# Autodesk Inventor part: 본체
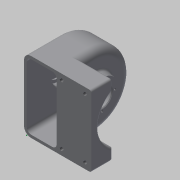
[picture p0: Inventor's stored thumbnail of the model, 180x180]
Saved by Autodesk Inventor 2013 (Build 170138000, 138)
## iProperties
Created: 2015-02
Part Number: 본체
Material: 일반
Document SubType Name: Modeling
Designer: Administrator
Density: 1 g/cm^3
Author: Administrator
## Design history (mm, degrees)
sketch "스케치1"
  geometry: L1 (0, 0)-(95, 0); L2 (95, 0)-(95, 100); L3 (95, 100)-(0, 100); L4 (0, 100)-(0, 0); 4 further points
  constraints: 8 end point, 2 parallel, 1 horizontal, 1 perpendicular
  dimensions: "d0" = 100 distance of L1.end L2.end; "d2" = 95 distance of L2.end L3.end; "d3" = 9 distance from line of L4 point (9, 91.75); "d4" = 33 distance of point (9, 91.75) point (42, 91.75); "d5" = 9 distance from line of L4 point (9, 8.25); "d6" = 33 distance of point (9, 8.25) point (42, 8.25); "d7" = 83.5 distance of point (9, 91.75) point (9, 8.25); "d8" = 8.25 distance from line of L3 point (9, 91.75); "d9" = 8.25 distance from line of L1 point (42, 8.25); "d10" = 8.25 distance from line of L3 point (42, 91.75)
extrude "돌출1" new body sketch "스케치1" distance "d11" = 30; taper "d12" = 0 deg
node "작업 평면1"
sketch "스케치2"
  geometry: L1 (0, 30)-(100, 30) reference; L2 (0, 0)-(0, 30) reference; L3 (100, 0)-(100, 30) reference; L4 (0, 0)-(100, 0) reference; C1 r 50 at (50, 50); C2 r 20 at (50, 50); 1 further point
  constraints: 2 centre point, 1 coincident, 1 midpoint, 1 vertical alignment
  dimensions: "d14" = 100 diameter of C1; "d16" = 50 distance from line of L4 C1.centre; "d17" = 40 diameter of C2
extrude "돌출2" join sketch "스케치2" distance "d18" = 50; taper "d19" = 0 deg
extrude "돌출3" join sketch "스케치2" distance "d20" = 9; taper "d21" = 0 deg
node "작업 평면2"
sketch "스케치3"
  geometry: L1 (-45, 4.174)-(-45, 95.826) reference; L2 (-45, 50)-(-35, 50); L3 (-35, 50)-(-35, 73.237); L4 (-35, 73.237)-(-45, 75); 1 further point
  constraints: 6 end point, 2 perpendicular, 1 midpoint, 1 point on line
  dimensions: "d23" = 50 diameter of L4.end L2; "d25" = 100 deg angle of L1 L4; "d27" = 10 distance of L2.start L2.end
revolve "회전1" stored, may be unused: angle "d28" = 90 deg
sketch "스케치4"
  geometry: L1 (0, 30)-(4.174, 30) reference; L2 (0, 0)-(0, 30) reference; L3 (0, 30)-(0, 50); L4 (100, 0)-(100, 30) reference; L5 (95.826, 30)-(100, 30) reference; L6 (100, 30)-(100, 50); L7 (100, 30)-(0, 30); A1 r 50 centre (50, 50) between (4.174, 30) and (0, 50) reference; A2 r 50 centre (50, 50) between (0, 50) and (100, 50); A3 r 50 centre (50, 50) between (95.826, 30) and (4.174, 30) reference
  constraints: 6 end point, 4 point on circle, 2 tangent, 1 centre point, 1 coincident, 1 perpendicular
extrude "돌출4" join sketch "스케치4" distance "d29" = 50; taper "d30" = 0 deg
node "작업 평면3"
sketch "스케치5"
  geometry: C1 r 40 at (50, 50); A1 r 50 centre (50, 50) between (100, 50) and (0, 50) reference; 1 further point
  constraints: 1 centre point, 1 coincident
extrude "돌출5" cut sketch "스케치5" distance "d32" = 45; taper "d33" = 0 deg
revolve "회전2" stored, may be unused: angle "d34" = 90 deg
node "작업 평면4"
sketch "스케치6"
  geometry: L1 (0, 0)-(0, 30) reference; L2 (100, 0)-(0, 0) reference; L3 (0, 30)-(0, 50) reference; L4 (100, 50)-(100, 30) reference; L5 (100, 0)-(100, 30) reference; L6 (4, 4)-(96, 4); L7 (4, 4)-(4, 50); L8 (96, 4)-(96, 50); A1 r 50 centre (50, 50) between (100, 50) and (0, 50) reference; A2 r 46 centre (50, 50) between (96, 50) and (4, 50)
  constraints: 6 end point, 2 perpendicular, 2 point on circle, 1 centre point, 1 coincident, 1 parallel
  dimensions: "d35" = 4 distance between parallel lines of L2 L6; "d36" = 4 distance between parallel lines of L1 L7; "d37" = 4 distance between parallel lines of L5 L8; "d38" = 4 radial gap between concentric circles of A2 A1
extrude "돌출6" cut sketch "스케치6" stored distance "d39" = 42; taper "d40" = 0 deg
hole "구멍1" diameter "d43" = 28; stored, may be unused: countersink angle "d47" = 90 deg, drill point angle "d49" = 0 deg; dims "d41" = 10, "d42" = 10, "d44" = 6, "d45" = 4, "d46" = 2, "d48" = 10
hole "구멍2" diameter "d52" = 20; stored, may be unused: countersink angle "d56" = 90 deg, drill point angle "d58" = 0 deg; dims "d50" = 10, "d51" = 10, "d53" = 6, "d54" = 4, "d55" = 2, "d57" = 4
sketch "스케치7"
  geometry: L1 (0, 0)-(-95, 0) reference; L2 (-95, 100)-(0, 100) reference; L3 (-95, 0)-(-95, 100) reference; L4 (-91, 96)-(-91, 4); L5 (-91, 4)-(-49, 4); L6 (-49, 4)-(-49, 96); L7 (-49, 96)-(-91, 96)
  constraints: 8 end point, 3 parallel, 1 perpendicular
  dimensions: "d59" = 4 distance between parallel lines of L1 L5; "d60" = 4 distance between parallel lines of L3 L4; "d61" = 4 distance between parallel lines of L2 L7; "d62" = 42 distance between parallel lines of L4 L6
extrude "돌출7" cut sketch "스케치7" distance "d63" = 10; taper "d64" = 0 deg
sketch "스케치8"
  geometry: A1 r 46 centre (-50, 50) between (-4, 50) and (-96, 50) reference; 2 further points
  constraints: 1 coincident
hole "구멍3" sketch "스케치8" diameter "d65" = 28; stored, may be unused: countersink angle "d69" = 90 deg, drill point angle "d71" = 0 deg; dims "d66" = 6, "d67" = 4, "d68" = 2, "d70" = 8
hole "구멍4" sketch "스케치8" diameter "d72" = 20; stored, may be unused: countersink angle "d76" = 90 deg, drill point angle "d78" = 0 deg; dims "d73" = 6, "d74" = 4, "d75" = 2, "d77" = 10
hole "구멍5" sketch "스케치1" diameter "d79" = 5.134; stored, may be unused: countersink angle "d83" = 90 deg, drill point angle "d85" = 118 deg; dims "d80" = 10, "d81" = 4, "d82" = 2, "d84" = 13
sketch "스케치9"
  geometry: L1 (0, 0)-(-18, 0); L2 (0, 0)-(0, 18); L3 (0, 0)-(18, 0); L4 (0, 0)-(0, -18); C1 r 23.237 at (0, 0) reference; A1 r 18 centre (0, 0) between (-18, 0) and (0, 18); 5 further points
  constraints: 8 end point, 5 coincident, 4 point on circle, 3 perpendicular, 1 centre point, 1 horizontal
  dimensions: "d86" = 36 diameter of A1
hole "구멍6" sketch "스케치9" at (0, 18), (-18, 0), (0, -18), (18, 0) diameter "d88" = 2.459; stored, may be unused: countersink angle "d92" = 90 deg, drill point angle "d94" = 118 deg; dims "d89" = 6, "d90" = 4, "d91" = 2, "d93" = 9
chamfer "모따기1" distance "d95" = 1; stored, may be unused: second distance "d96" = 2, angle "d97" = 45 deg
chamfer "모따기2" distance "d98" = 1; stored, may be unused: second distance "d99" = 2, angle "d100" = 45 deg
fillet "모깎기1" dims "d101" = 0.3
fillet "모깎기2" dims "d102" = 0.3
fillet "모깎기3" dims "d103" = 6
fillet "모깎기4" dims "d104" = 10
fillet "모깎기5" dims "d105" = 3
fillet "모깎기6" dims "d106" = 3
fillet "모깎기7" dims "d107" = 3
node "솔리드1"
other parameters: "d13" = 0, "d31" = 0
